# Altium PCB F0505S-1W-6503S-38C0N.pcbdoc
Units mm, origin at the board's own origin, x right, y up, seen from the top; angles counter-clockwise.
Board outline 31.54 x 25.78 mm, 2 copper layers (Top Layer, Bottom Layer); 12 components, 10 nets, 33 pads, 16 vias.
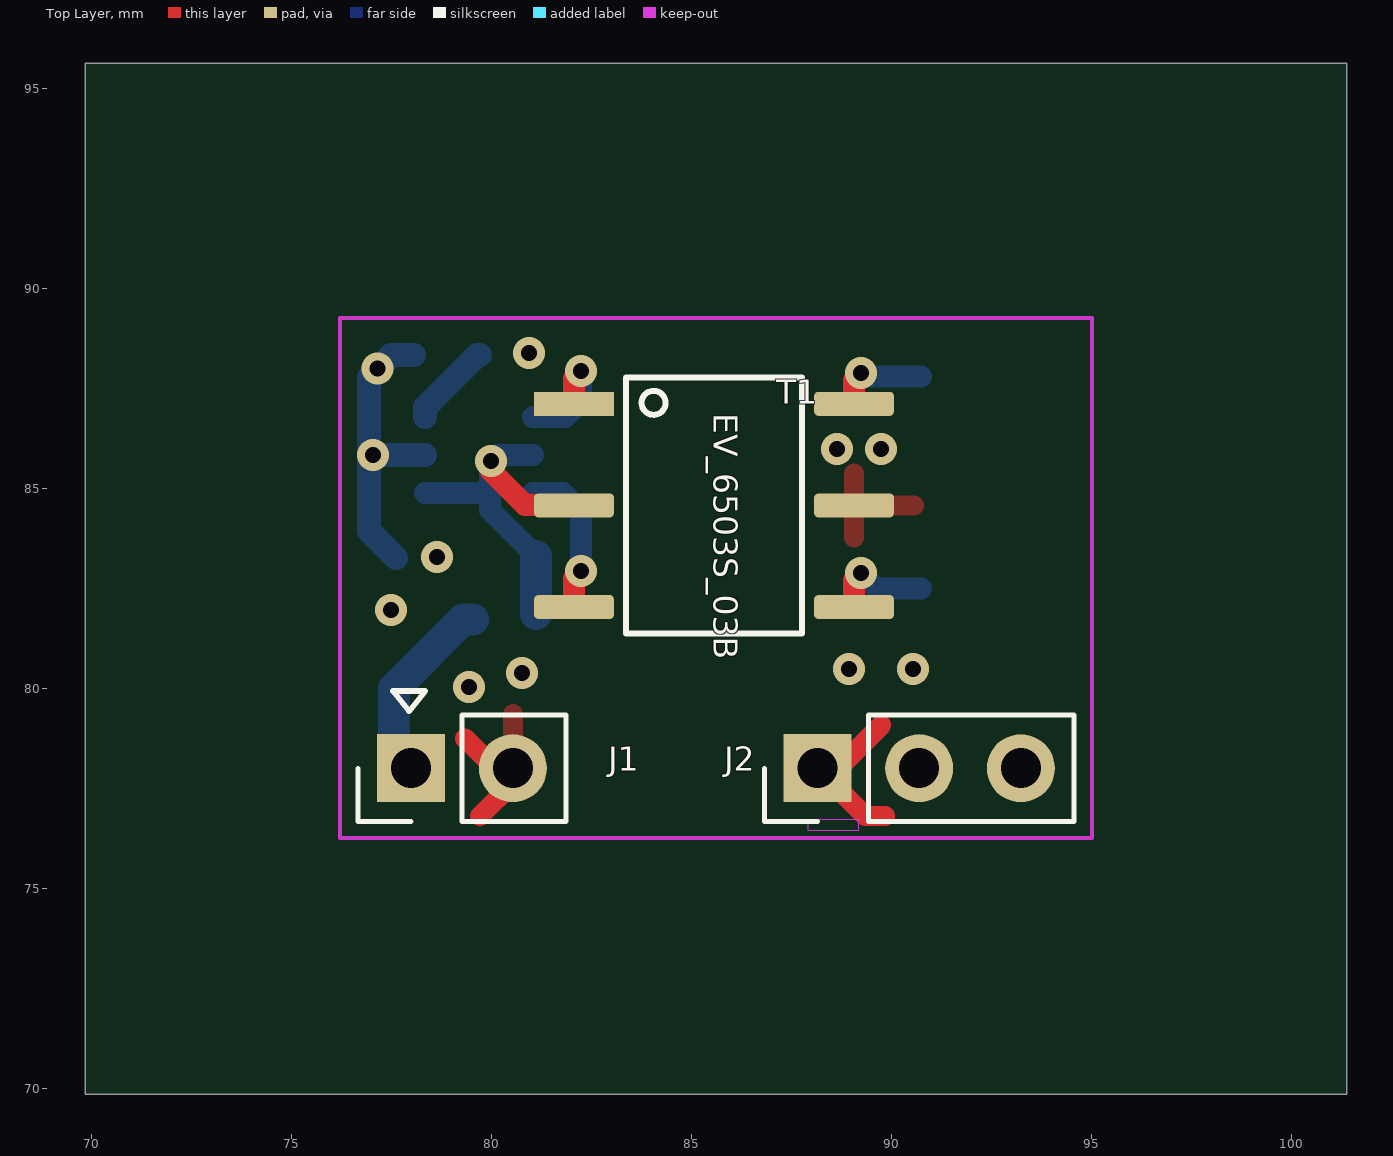
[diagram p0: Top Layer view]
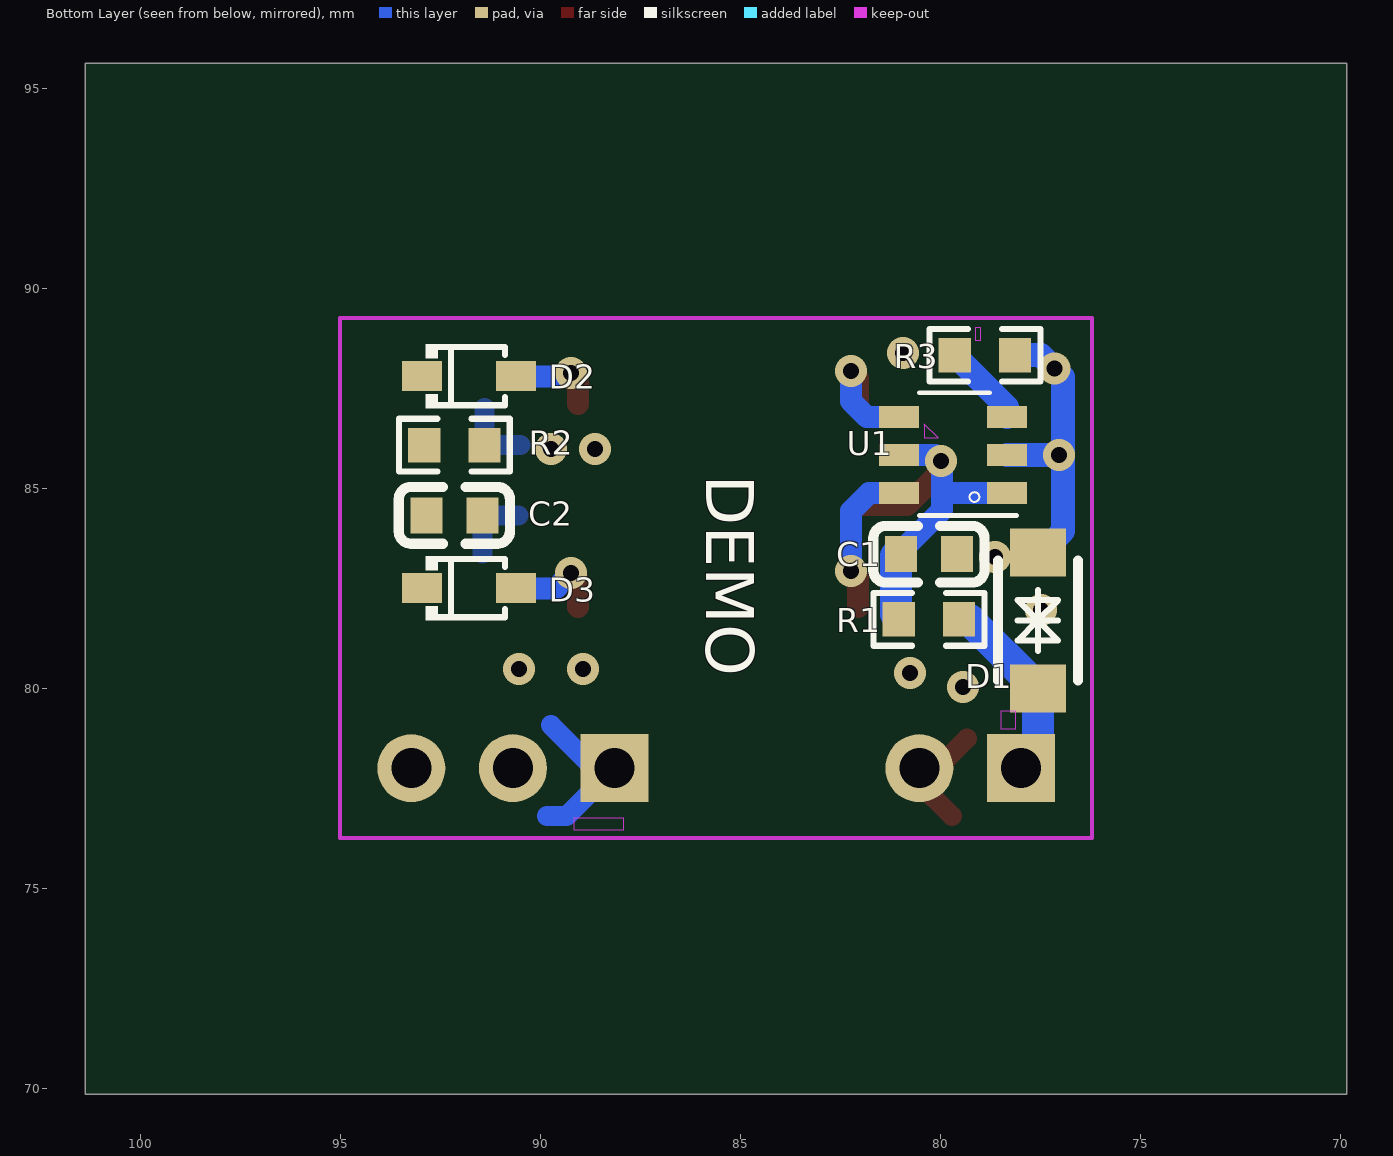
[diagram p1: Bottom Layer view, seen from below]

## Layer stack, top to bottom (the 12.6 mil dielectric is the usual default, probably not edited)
Top Layer: signal copper (thickness not stored)
Dielectric: dielectric 0.32, FR-4, Dk 4.8
Bottom Layer: signal copper (thickness not stored)

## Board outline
101.391,69.85 69.85,69.85 69.85,95.625 101.391,95.625

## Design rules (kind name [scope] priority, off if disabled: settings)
BoardOutlineClearance safeClearance [All] p0: genericclearance=0.254 ignorepadtopadclearanceinfootprint=FALSE except(0: Track-CutoutEdge SMDPad-CutoutEdge THPad-CutoutEdge Via-CutoutEdge Fill-CutoutEdge Region-CutoutEdge Arc-SplitContinuation Track-SplitContinuation SMDPad-SplitContinuation THPad-SplitContinuation Via-SplitContinuation Fill-SplitContinuation Poly-SplitContinuation Region-SplitContinuation Text-SplitContinuation; 0.3: Track-OutlineEdge SMDPad-OutlineEdge THPad-OutlineEdge Via-OutlineEdge Fill-OutlineEdge Region-OutlineEdge Poly-OutlineEdge Text-OutlineEdge)
Clearance safeClearance [(InNet('0V') OR InNet('GND') OR InNet('+VO') OR InNet('VD1') OR InNet('VD2') OR InNet('VIN') OR InNet('VCC') OR InNet('CLK') OR InNet('$1N10') OR InNet('$1N16'))] p1: gap=0.178 ignorepadtopadclearanceinfootprint=FALSE except(0: Track-Track Track-SMDPad SMDPad-SMDPad Track-THPad SMDPad-THPad THPad-THPad Track-Via SMDPad-Via THPad-Via Via-Via Track-Fill SMDPad-Fill THPad-Fill Via-Fill Fill-Fill Track-Region SMDPad-Region THPad-Region Via-Region Fill-Region Region-Region Track-Poly SMDPad-Poly THPad-Poly Via-Poly Fill-Poly Region-Poly Poly-Poly Track-Text SMDPad-Text THPad-Text Via-Text Fill-Text Region-Text Poly-Text Text-Text Track-Hole SMDPad-Hole THPad-Hole Via-Hole Fill-Hole Region-Hole Poly-Hole Text-Hole; 0.3: Track-Sheet SMDPad-Sheet THPad-Sheet Via-Sheet Fill-Sheet Region-Sheet Poly-Sheet Text-Sheet Sheet-Hole)
DiffPairsRouting differentialPair [All] p1: maxuncoupledlength=10 minlimit=5.9843 maxlimit=5.9843 mostfreqgap=5.9843 toplayer_minwidth=5 toplayer_prefwidth=10 toplayer_maxwidth=100 bottomlayer_minwidth=5 bottomlayer_prefwidth=10 bottomlayer_maxwidth=100
PasteMaskExpansion Common [All] p1: expansion=0
PlaneConnect innerPlane [All] p1: planeconnectstyle=Relief reliefexpansion=0.508 reliefentries=4 reliefconductorwidth=0.254 reliefairgap=0.254
PolygonConnect CopperRegion [All] p1: connectstyle=Relief reliefentries=4 reliefconductorwidth=0 polygonreliefangle="90 Angle" airgapwidth=9.8031
PolygonConnect CopperRegion1 [All] p1: connectstyle=Relief reliefentries=4 reliefconductorwidth=19.685 polygonreliefangle="90 Angle" airgapwidth=19.685
PolygonConnect CopperRegion2 [All] p1: connectstyle=Direct reliefentries=4 reliefconductorwidth=0 polygonreliefangle="90 Angle" airgapwidth=17.7165
PolygonConnect CopperRegion3 [All] p1: connectstyle=Direct reliefentries=4 reliefconductorwidth=0 polygonreliefangle="90 Angle" airgapwidth=9.8031
PolygonConnect CopperRegion4 [All] p1: connectstyle=Relief reliefentries=4 reliefconductorwidth=0 polygonreliefangle="90 Angle" airgapwidth=9.8031
RoutingVias viaSize [All] p1: viastyle="Through Hole" holewidth=12.0078 minholewidth=11.811 maxholewidth=236.1812 width=24.0158 minwidth=19.685 maxwidth=393.7008
SolderMaskExpansion Common [All] p1: useseparateexpansions=TRUE expansion=0 expansionbottom=0
Width trackWidth [All] p1: maxlimit=100 minlimit=5 preferedwidth=10

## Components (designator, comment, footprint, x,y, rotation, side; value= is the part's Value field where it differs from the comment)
C1 "0603X106K100NT" C0603 80.3,83.35 r0 bottom
C2 "0603X106K100NT" C0603 92.165,84.323 r0 bottom
D1 "NC" SOD-123FL_L2.8-W1.8-LS3.7-BI 77.575,81.696 r90 bottom
D2 "B5819WS_C64886" SOD-323_L1.8-W1.3-LS2.5-RD 91.8,87.8 r180 bottom
D3 "B5819WS_C64886" SOD-323_L1.8-W1.3-LS2.5-RD 91.8,82.5 r180 bottom
J1 "Connector_Generic_Conn_01x04" coileasy:PinHeader_01x02_P2.54mm_Vertical 78,78 r90 top
J2 "Connector_Generic_Conn_01x04" coileasy:PinHeader_01x03_1_P2.54mm_Vertical 88.16,78 r90 top
R1 "RC0603FR-070RL" R0603 80.3,81.723 r0 bottom
R2 "RC0603FR-074K7L" R0603 92.165,86.077 r180 bottom
R3 "R" R0603 78.9,88.325 r180 bottom
T1 "CMT38C0N" coileasy:CMT38xxx 85.57,84.57 r0 top
U1 "CMP6503S" coileasy:SOT-23-6 79.542,85.796 r0 bottom

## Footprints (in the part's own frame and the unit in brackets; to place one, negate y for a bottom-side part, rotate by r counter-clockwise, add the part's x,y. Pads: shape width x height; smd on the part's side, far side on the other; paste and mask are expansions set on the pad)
C0603 [mm]
  rect 0.8x0.9 smd: 1(-0.7,0) 2(0.7,0)
  silkscreen extent -1.39,-0.71 1.39,0.71
coileasy:CMT38xxx [mm]
  rect 2x0.6 smd: 1(-3.5,2.54)
  rrect37% 2x0.6 smd: 2(-3.5,0) 3(-3.5,-2.54) 4(3.5,-2.54) 5(3.5,0) 6(3.5,2.54)
  silkscreen extent -2.2,-3.2 2.2,3.2
coileasy:PinHeader_01x02_P2.54mm_Vertical [mm]
  rect 1.7x1.7 hole 1: 1(0,0)
  round 1.7 hole 1: 2(0,-2.54)
  silkscreen extent -1.33,-3.87 1.33,1.33
coileasy:PinHeader_01x03_1_P2.54mm_Vertical [mm]
  rect 1.7x1.7 hole 1: 5(0,0)
  round 1.7 hole 1: 6(0,-2.54) 7(0,-5.08)
  silkscreen extent -1.33,-6.41 1.33,1.33
coileasy:SOT-23-6 [mm]
  rect 1x0.55 smd: 1(-1.192,0.921) 2(-1.192,-0.029) 3(-1.192,-0.979) 4(1.508,-0.979) 5(1.508,-0.029) 6(1.508,0.921)
  silkscreen extent -1.43,-1.59 1,1.48
R0603 [mm]
  rect 0.806x0.864 smd: 1(-0.753,0) 2(0.753,0)
  silkscreen extent -1.39,-0.66 1.39,0.66
SOD-123FL_L2.8-W1.8-LS3.7-BI [mm]
  rect 1.2x1.4 smd: 1(-1.7,0) 2(1.7,0)
  silkscreen extent -1.5,-1 1.5,1
SOD-323_L1.8-W1.3-LS2.5-RD [mm]
  rect 1x0.75 smd: 1(-1.173,0) 2(1.173,0)
  silkscreen extent -1.08,-0.8 0.9,0.8

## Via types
v1: diameter 0.8, hole 0.4, Top Layer to Bottom Layer, 16 vias

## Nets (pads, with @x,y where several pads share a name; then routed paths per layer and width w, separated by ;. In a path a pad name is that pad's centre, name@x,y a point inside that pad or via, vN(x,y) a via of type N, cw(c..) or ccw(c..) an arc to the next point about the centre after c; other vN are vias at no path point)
0V: C2.1 J2.5 R2.2 T1.5 | length 9.5
  Top Layer w0.5: J2.5@88.525,78 J2.5 ; J2.5@88.775,78 J2.5 ; 89.75,79.075 88.675,78 J2.5 ; 89.85,76.801 89.359,76.801 J2.5
  Bottom Layer w0.5: J2.5@88.375,77.925 J2.5@88.375,78.025 ; 89.75,79.075 88.675,78 J2.5 89.359,76.801 89.85,76.801
  other v1: 88.95,80.475 90.55,80.475 88.65,85.975 89.75,85.975
$1N10: D2.2 T1.6 | length 2.4
  Top Layer w0.55: T1.6 89.07,87.695 v1(89.25,87.875)
  Bottom Layer w0.55: v1(89.25,87.875) 89.335,87.79 D2.2@90.75,87.79
$1N16: D3.2 T1.4 | length 2.6
  Top Layer w0.55: T1.4 89.07,82.695 v1(89.25,82.875)
  Bottom Layer w0.55: v1(89.25,82.875) 89.635,82.49 D3.2@90.75,82.49
+VO: C2.2 D2.1 D3.1 J2.7 R2.1
CLK: R3.1 U1.3 | length 2.2
  Bottom Layer w0.6: U1.3 78.35,87.025 79.65,88.325 R3.1@79.725,88.325
GND: C1.1 D1.2 J1.2 R3.2 U1.2 | length 10.6
  Top Layer w0.5: 79.35,78.745 80.095,78 J1.2 80.54,77.625 79.72,76.805
  Bottom Layer w0.6: D1.2@77.625,83.25 76.95,83.925 v1@76.95,85.8 ; R3.2@78.075,88.325 77.5,88.325 v1(77.162,87.987) 76.95,87.775 v1@76.95,85.8 ; U1.2 v1(77.05,85.825) 76.975,85.825 v1@76.95,85.8
  other v1: 79.45,80.025 80.775,80.375 77.5,81.95 78.65,83.275 80.95,88.375
VCC: C1.2 R1.2 T1.2 U1.1 U1.5 | length 9.7
  Top Layer w0.55: v1(80,85.675) 80,85.425 80.85,84.575 T1.2@82.075,84.575
  Bottom Layer w0.55: U1.1 79.975,84.875 ; C1.2@81.025,83.35 81.075,83.35 79.975,84.45 79.975,84.875 ; U1.5 80.15,85.825 v1(80,85.675) 79.975,85.65 79.975,84.875
  Bottom Layer w0.8: R1.2@81.125,81.85 C1.2@81.125,83.3
VD1: T1.3 U1.6 | length 3.9
  Top Layer w0.55: T1.3 82.07,82.745 v1(82.25,82.925)
  Bottom Layer w0.55: U1.6 81.8,84.875 82.25,84.425 v1(82.25,82.925)
VD2: T1.1 U1.4 | length 3
  Top Layer w0.55: T1.1 82.07,87.745 v1(82.25,87.925)
  Bottom Layer w0.55: U1.4 81.85,86.775 82.25,87.175 v1(82.25,87.925)
VIN: D1.1 J1.1 R1.1 | length 4.9
  Bottom Layer w0.8: J1.1 77.575,78.425 D1.1 79.302,81.723 R1.1
pads on no net: J2.6

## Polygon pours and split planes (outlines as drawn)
0V on Top Layer (solid, remove dead copper, pour order 4): 88.056,79.643 88.437,79.643 88.437,78.373 88.056,78.373
0V on Bottom Layer (solid, remove dead copper, pour order 12): 88.056,79.643 88.437,79.643 88.437,78.373 88.056,78.373
0V on Top Layer (solid, remove dead copper, pour order 0): 95.014,89.25 88.05,89.275 88.05,76.275 95.039,76.25
+VO on Bottom Layer (solid, remove dead copper, pour order 6): 92.75,88.95 94.65,88.95 94.65,76.25 92.75,76.275
0V on Bottom Layer (solid, remove dead copper, pour order 8): 95.016,89.25 88.05,89.275 88.05,76.275 95.041,76.25
GND on Top Layer (solid, remove dead copper, pour order 2): 76.225,89.225 81.6,89.25 81.625,76.25 76.225,76.25
GND on Bottom Layer (solid, remove dead copper, pour order 10): 76.225,89.225 81.6,89.25 81.625,76.25 76.225,76.25

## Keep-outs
Top Layer:
  region: 87.929,76.73 89.174,76.73 89.174,76.443 87.929,76.443
Bottom Layer:
  region: 87.929,76.746 89.174,76.746 89.174,76.459 87.929,76.459
  region: 79.002,89.016 79.141,89.016 79.141,88.706 79.002,88.706
  region: 78.125,79.425 78.499,79.425 78.499,78.983 78.125,78.983
  region: 80.071,86.263 80.411,86.603 80.411,86.263
Board Outline Layer:
  lines w0.1: 76.225,76.25 95.025,76.25 95.025,89.25 76.225,89.25 76.225,76.25

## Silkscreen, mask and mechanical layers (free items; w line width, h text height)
Top Silkscreen Layer:
  lines w0.15: 77.55,79.925 78.35,79.925 77.95,79.425 77.55,79.925
  text "EV_6503S_03B" at 85.558,86.875 h0.6 r270
Bottom Silkscreen Layer:
  text "DEMO" at 85.872,85.333 h1.2 r90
